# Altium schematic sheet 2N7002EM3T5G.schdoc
size 127 x 101 mm
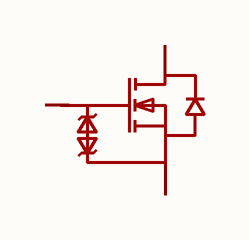
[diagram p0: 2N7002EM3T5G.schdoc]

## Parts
Q?  2n7002em3t5g  [SOT-723_L1.2-W0.8-P0.40-LS1.2-BR]  (value not drawn)

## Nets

Not connected (* = marked no-connect by the designer): Q? 1(G) 2(S) 3(D)

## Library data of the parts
Q? = 2n7002em3t5g: 数量:1个N沟道;漏源电压(Vdss):60V;连续漏极电流(Id):350mA;导通电阻(RDS(on)):5Ω@10V;耗散功率(Pd):150mW;阈值电压(Vgs(th)):1.85V@250uA;; Manufacturer: TECH PUBLIC(台舟); AddInBom: yes; ModelId: abccde1e67074d7481274a37cf5c97f0; ModelName: SOT-723-3P_L1.2-W0.8-H0.6-LS1.2-P0.40; ModelTransform: 47.244,47.244,0,180,0,0,0,0,0; Number: 1个N沟道; Drain to Source Voltage: 60V; Current - Continuous Drain(Id): 350mA; RDS(on): 5Ω@10V; Pd - Power Dissipation: 150mW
